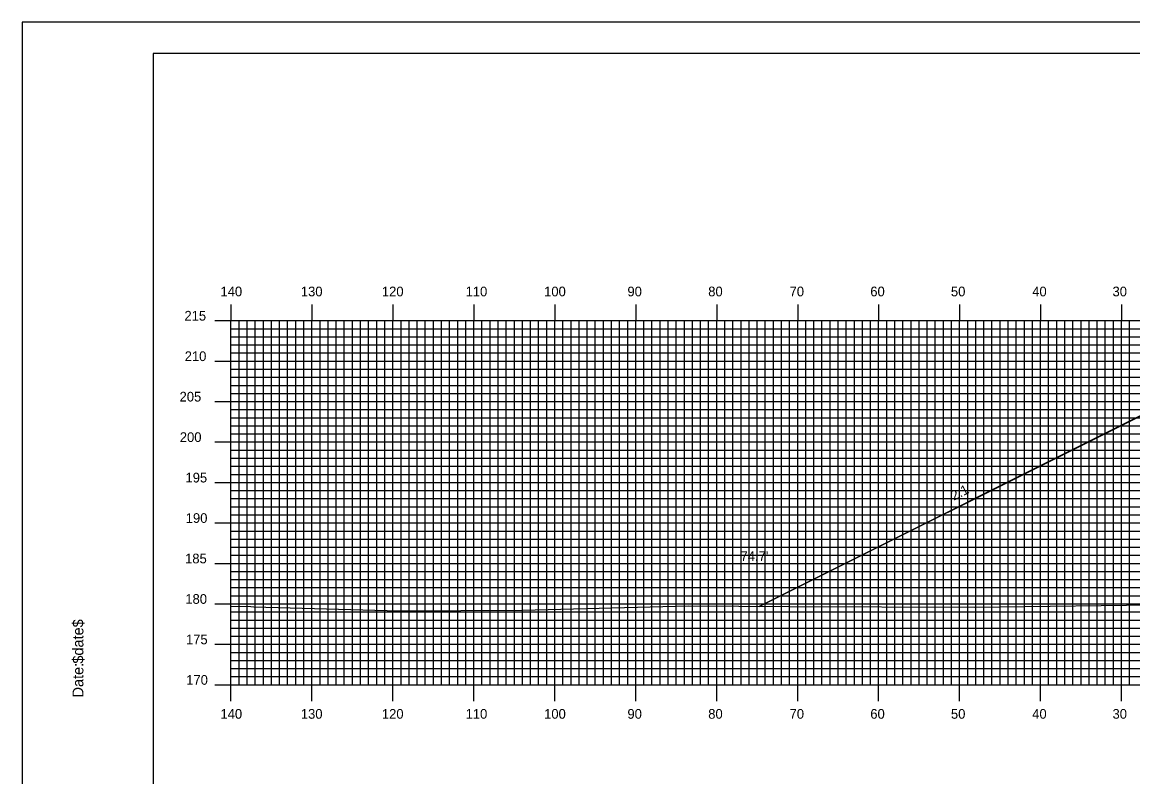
# Model space of a CAD drawing. Extents: x 1809406 to 1809749, y 442591 to 442811.
# Drawn here: x 1809406.1 to 1809543.2, y 442717.3 to 442810.5 of the extents above; entities that cross this region are included whole.
import ezdxf

# ---------------------------------------------------------------- set-up
doc = ezdxf.new("R2010")
doc.units = 0
for name, color, linetype in [('ANNOTATION', 7, 'Continuous'), ('BORDER', 7, 'Continuous'), ('D_Roadway_Centerline', 7, 'Continuous'), ('D_Roadway_SlopeLines', 7, 'Continuous'), ('D_Text_Standard', 7, 'Continuous'), ('H_V ANNOTATION', 7, 'Continuous'), ('MAJOR', 7, 'Continuous'), ('MINOR', 7, 'Continuous'), ('PLOT BOUNDARY', 7, 'Continuous'), ('S_Roadway_Centerline', 7, 'Continuous')]:
    doc.layers.add(name, color=color, linetype=linetype)

msp = doc.modelspace()

# ---------------------------------------------------------------- linework, layer by layer
at = {"layer": 'BORDER'}
msp.add_lwpolyline([(1809422.24, 442596.67), (1809742.24, 442596.67), (1809742.24, 442806.67), (1809422.24, 442806.67)], close=True, dxfattribs=at)
at = {"layer": 'D_Roadway_Centerline'}
msp.add_lwpolyline([(1809497.1, 442738.36), (1809543.63, 442761.62), (1809548.84, 442764.23), (1809551.84, 442764.29), (1809559.84, 442764.45), (1809571.84, 442763.87), (1809583.84, 442763.29), (1809591.84, 442762.91), (1809594.84, 442762.77), (1809600.37, 442760), (1809642.88, 442738.74)], dxfattribs=at)
at = {"layer": 'D_Roadway_SlopeLines'}
msp.add_lwpolyline([(1809548.84, 442764.23), (1809497.1, 442738.36)], dxfattribs=at)
at = {"layer": 'MAJOR'}
for p, q in [((1809431.84, 442775.67), (1809431.84, 442773.67)), ((1809441.84, 442775.67), (1809441.84, 442773.67)), ((1809451.84, 442775.67), (1809451.84, 442773.67)), ((1809461.84, 442775.67), (1809461.84, 442773.67)), ((1809471.84, 442775.67), (1809471.84, 442773.67)), ((1809481.84, 442775.67), (1809481.84, 442773.67)), ((1809491.84, 442775.67), (1809491.84, 442773.67)), ((1809501.84, 442775.67), (1809501.84, 442773.67)), ((1809511.84, 442775.67), (1809511.84, 442773.67)), ((1809521.84, 442775.67), (1809521.84, 442773.67)), ((1809531.84, 442775.67), (1809531.84, 442773.67)), ((1809541.84, 442775.67), (1809541.84, 442773.67)), ((1809429.83, 442773.67), (1809431.84, 442773.67)), ((1809431.84, 442773.67), (1809711.84, 442773.67)), ((1809431.84, 442728.67), (1809431.84, 442773.67)), ((1809431.84, 442728.67), (1809431.84, 442773.67)), ((1809431.84, 442773.67), (1809711.84, 442773.67)), ((1809441.84, 442728.67), (1809441.84, 442773.67)), ((1809451.84, 442728.67), (1809451.84, 442773.67)), ((1809461.84, 442728.67), (1809461.84, 442773.67)), ((1809471.84, 442728.67), (1809471.84, 442773.67)), ((1809481.84, 442728.67), (1809481.84, 442773.67)), ((1809491.84, 442728.67), (1809491.84, 442773.67)), ((1809501.84, 442728.67), (1809501.84, 442773.67)), ((1809511.84, 442728.67), (1809511.84, 442773.67)), ((1809521.84, 442728.67), (1809521.84, 442773.67)), ((1809531.84, 442728.67), (1809531.84, 442773.67)), ((1809541.84, 442728.67), (1809541.84, 442773.67)), ((1809429.83, 442768.67), (1809431.84, 442768.67)), ((1809431.84, 442768.67), (1809711.84, 442768.67)), ((1809429.83, 442763.67), (1809431.84, 442763.67)), ((1809431.84, 442763.67), (1809711.84, 442763.67)), ((1809429.83, 442758.67), (1809431.84, 442758.67)), ((1809431.84, 442758.67), (1809711.84, 442758.67)), ((1809429.83, 442753.67), (1809431.84, 442753.67)), ((1809431.84, 442753.67), (1809711.84, 442753.67)), ((1809429.83, 442748.67), (1809431.84, 442748.67)), ((1809431.84, 442748.67), (1809711.84, 442748.67)), ((1809429.83, 442743.67), (1809431.84, 442743.67)), ((1809431.84, 442743.67), (1809711.84, 442743.67)), ((1809429.83, 442738.67), (1809431.84, 442738.67)), ((1809431.84, 442738.67), (1809711.84, 442738.67)), ((1809429.83, 442733.67), (1809431.84, 442733.67)), ((1809431.84, 442733.67), (1809711.84, 442733.67)), ((1809429.83, 442728.67), (1809431.84, 442728.67)), ((1809431.84, 442728.67), (1809711.84, 442728.67)), ((1809431.84, 442728.67), (1809711.84, 442728.67)), ((1809431.84, 442726.66), (1809431.84, 442728.67)), ((1809441.84, 442726.66), (1809441.84, 442728.67)), ((1809451.84, 442726.66), (1809451.84, 442728.67)), ((1809461.84, 442726.66), (1809461.84, 442728.67)), ((1809471.84, 442726.66), (1809471.84, 442728.67)), ((1809481.84, 442726.66), (1809481.84, 442728.67)), ((1809491.84, 442726.66), (1809491.84, 442728.67)), ((1809501.84, 442726.66), (1809501.84, 442728.67)), ((1809511.84, 442726.66), (1809511.84, 442728.67)), ((1809521.84, 442726.66), (1809521.84, 442728.67)), ((1809531.84, 442726.66), (1809531.84, 442728.67)), ((1809541.84, 442726.66), (1809541.84, 442728.67))]:
    msp.add_line(p, q, dxfattribs=at)
at = {"layer": 'MINOR'}
for p, q in [((1809432.84, 442728.67), (1809432.84, 442773.67)), ((1809433.84, 442728.67), (1809433.84, 442773.67)), ((1809434.84, 442728.67), (1809434.84, 442773.67)), ((1809435.84, 442728.67), (1809435.84, 442773.67)), ((1809436.84, 442728.67), (1809436.84, 442773.67)), ((1809437.84, 442728.67), (1809437.84, 442773.67)), ((1809438.84, 442728.67), (1809438.84, 442773.67)), ((1809439.84, 442728.67), (1809439.84, 442773.67)), ((1809440.84, 442728.67), (1809440.84, 442773.67)), ((1809442.84, 442728.67), (1809442.84, 442773.67)), ((1809443.84, 442728.67), (1809443.84, 442773.67)), ((1809444.84, 442728.67), (1809444.84, 442773.67)), ((1809445.84, 442728.67), (1809445.84, 442773.67)), ((1809446.84, 442728.67), (1809446.84, 442773.67)), ((1809447.84, 442728.67), (1809447.84, 442773.67)), ((1809448.84, 442728.67), (1809448.84, 442773.67)), ((1809449.84, 442728.67), (1809449.84, 442773.67)), ((1809450.84, 442728.67), (1809450.84, 442773.67)), ((1809452.84, 442728.67), (1809452.84, 442773.67)), ((1809453.84, 442728.67), (1809453.84, 442773.67)), ((1809454.84, 442728.67), (1809454.84, 442773.67)), ((1809455.84, 442728.67), (1809455.84, 442773.67)), ((1809456.84, 442728.67), (1809456.84, 442773.67)), ((1809457.84, 442728.67), (1809457.84, 442773.67)), ((1809458.84, 442728.67), (1809458.84, 442773.67)), ((1809459.84, 442728.67), (1809459.84, 442773.67)), ((1809460.84, 442728.67), (1809460.84, 442773.67)), ((1809462.84, 442728.67), (1809462.84, 442773.67)), ((1809463.84, 442728.67), (1809463.84, 442773.67)), ((1809464.84, 442728.67), (1809464.84, 442773.67)), ((1809465.84, 442728.67), (1809465.84, 442773.67)), ((1809466.84, 442728.67), (1809466.84, 442773.67)), ((1809467.84, 442728.67), (1809467.84, 442773.67)), ((1809468.84, 442728.67), (1809468.84, 442773.67)), ((1809469.84, 442728.67), (1809469.84, 442773.67)), ((1809470.84, 442728.67), (1809470.84, 442773.67)), ((1809472.84, 442728.67), (1809472.84, 442773.67)), ((1809473.84, 442728.67), (1809473.84, 442773.67)), ((1809474.84, 442728.67), (1809474.84, 442773.67)), ((1809475.84, 442728.67), (1809475.84, 442773.67)), ((1809476.84, 442728.67), (1809476.84, 442773.67)), ((1809477.84, 442728.67), (1809477.84, 442773.67)), ((1809478.84, 442728.67), (1809478.84, 442773.67)), ((1809479.84, 442728.67), (1809479.84, 442773.67)), ((1809480.84, 442728.67), (1809480.84, 442773.67)), ((1809482.84, 442728.67), (1809482.84, 442773.67)), ((1809483.84, 442728.67), (1809483.84, 442773.67)), ((1809484.84, 442728.67), (1809484.84, 442773.67)), ((1809485.84, 442728.67), (1809485.84, 442773.67)), ((1809486.84, 442728.67), (1809486.84, 442773.67)), ((1809487.84, 442728.67), (1809487.84, 442773.67)), ((1809488.84, 442728.67), (1809488.84, 442773.67)), ((1809489.84, 442728.67), (1809489.84, 442773.67)), ((1809490.84, 442728.67), (1809490.84, 442773.67)), ((1809492.84, 442728.67), (1809492.84, 442773.67)), ((1809493.84, 442728.67), (1809493.84, 442773.67)), ((1809494.84, 442728.67), (1809494.84, 442773.67)), ((1809495.84, 442728.67), (1809495.84, 442773.67)), ((1809496.84, 442728.67), (1809496.84, 442773.67)), ((1809497.84, 442728.67), (1809497.84, 442773.67)), ((1809498.84, 442728.67), (1809498.84, 442773.67)), ((1809499.84, 442728.67), (1809499.84, 442773.67)), ((1809500.84, 442728.67), (1809500.84, 442773.67)), ((1809502.84, 442728.67), (1809502.84, 442773.67)), ((1809503.84, 442728.67), (1809503.84, 442773.67)), ((1809504.84, 442728.67), (1809504.84, 442773.67)), ((1809505.84, 442728.67), (1809505.84, 442773.67)), ((1809506.84, 442728.67), (1809506.84, 442773.67)), ((1809507.84, 442728.67), (1809507.84, 442773.67)), ((1809508.84, 442728.67), (1809508.84, 442773.67)), ((1809509.84, 442728.67), (1809509.84, 442773.67)), ((1809510.84, 442728.67), (1809510.84, 442773.67)), ((1809512.84, 442728.67), (1809512.84, 442773.67)), ((1809513.84, 442728.67), (1809513.84, 442773.67)), ((1809514.84, 442728.67), (1809514.84, 442773.67)), ((1809515.84, 442728.67), (1809515.84, 442773.67)), ((1809516.84, 442728.67), (1809516.84, 442773.67)), ((1809517.84, 442728.67), (1809517.84, 442773.67)), ((1809518.84, 442728.67), (1809518.84, 442773.67)), ((1809519.84, 442728.67), (1809519.84, 442773.67)), ((1809520.84, 442728.67), (1809520.84, 442773.67)), ((1809522.84, 442728.67), (1809522.84, 442773.67)), ((1809523.84, 442728.67), (1809523.84, 442773.67)), ((1809524.84, 442728.67), (1809524.84, 442773.67)), ((1809525.84, 442728.67), (1809525.84, 442773.67)), ((1809526.84, 442728.67), (1809526.84, 442773.67)), ((1809527.84, 442728.67), (1809527.84, 442773.67)), ((1809528.84, 442728.67), (1809528.84, 442773.67)), ((1809529.84, 442728.67), (1809529.84, 442773.67)), ((1809530.84, 442728.67), (1809530.84, 442773.67)), ((1809532.84, 442728.67), (1809532.84, 442773.67)), ((1809533.84, 442728.67), (1809533.84, 442773.67)), ((1809534.84, 442728.67), (1809534.84, 442773.67)), ((1809535.84, 442728.67), (1809535.84, 442773.67)), ((1809536.84, 442728.67), (1809536.84, 442773.67)), ((1809537.84, 442728.67), (1809537.84, 442773.67)), ((1809538.84, 442728.67), (1809538.84, 442773.67)), ((1809539.84, 442728.67), (1809539.84, 442773.67)), ((1809540.84, 442728.67), (1809540.84, 442773.67)), ((1809542.84, 442728.67), (1809542.84, 442773.67)), ((1809431.84, 442772.67), (1809711.84, 442772.67)), ((1809431.84, 442772.67), (1809433.84, 442772.67)), ((1809431.84, 442771.67), (1809711.84, 442771.67)), ((1809431.84, 442771.67), (1809433.84, 442771.67)), ((1809431.84, 442770.67), (1809711.84, 442770.67)), ((1809431.84, 442770.67), (1809433.84, 442770.67)), ((1809431.84, 442769.67), (1809711.84, 442769.67)), ((1809431.84, 442769.67), (1809433.84, 442769.67)), ((1809431.84, 442767.67), (1809711.84, 442767.67)), ((1809431.84, 442767.67), (1809433.84, 442767.67)), ((1809431.84, 442766.67), (1809711.84, 442766.67)), ((1809431.84, 442766.67), (1809433.84, 442766.67)), ((1809431.84, 442765.67), (1809711.84, 442765.67)), ((1809431.84, 442765.67), (1809433.84, 442765.67)), ((1809431.84, 442764.67), (1809711.84, 442764.67)), ((1809431.84, 442764.67), (1809433.84, 442764.67)), ((1809431.84, 442762.67), (1809711.84, 442762.67)), ((1809431.84, 442762.67), (1809433.84, 442762.67)), ((1809431.84, 442761.67), (1809711.84, 442761.67)), ((1809431.84, 442761.67), (1809433.84, 442761.67)), ((1809431.84, 442760.67), (1809711.84, 442760.67)), ((1809431.84, 442760.67), (1809433.84, 442760.67)), ((1809431.84, 442759.67), (1809711.84, 442759.67)), ((1809431.84, 442759.67), (1809433.84, 442759.67)), ((1809431.84, 442757.67), (1809711.84, 442757.67)), ((1809431.84, 442757.67), (1809433.84, 442757.67)), ((1809431.84, 442756.67), (1809711.84, 442756.67)), ((1809431.84, 442756.67), (1809433.84, 442756.67)), ((1809431.84, 442755.67), (1809711.84, 442755.67)), ((1809431.84, 442755.67), (1809433.84, 442755.67)), ((1809431.84, 442754.67), (1809711.84, 442754.67)), ((1809431.84, 442754.67), (1809433.84, 442754.67)), ((1809431.84, 442752.67), (1809711.84, 442752.67)), ((1809431.84, 442752.67), (1809433.84, 442752.67)), ((1809431.84, 442751.67), (1809711.84, 442751.67)), ((1809431.84, 442751.67), (1809433.84, 442751.67)), ((1809431.84, 442750.67), (1809711.84, 442750.67)), ((1809431.84, 442750.67), (1809433.84, 442750.67)), ((1809431.84, 442749.67), (1809711.84, 442749.67)), ((1809431.84, 442749.67), (1809433.84, 442749.67)), ((1809431.84, 442747.67), (1809711.84, 442747.67)), ((1809431.84, 442747.67), (1809433.84, 442747.67)), ((1809431.84, 442746.67), (1809711.84, 442746.67)), ((1809431.84, 442746.67), (1809433.84, 442746.67)), ((1809431.84, 442745.67), (1809711.84, 442745.67)), ((1809431.84, 442745.67), (1809433.84, 442745.67)), ((1809431.84, 442744.67), (1809711.84, 442744.67)), ((1809431.84, 442744.67), (1809433.84, 442744.67)), ((1809431.84, 442742.67), (1809711.84, 442742.67)), ((1809431.84, 442742.67), (1809433.84, 442742.67)), ((1809431.84, 442741.67), (1809711.84, 442741.67)), ((1809431.84, 442741.67), (1809433.84, 442741.67)), ((1809431.84, 442740.67), (1809711.84, 442740.67)), ((1809431.84, 442740.67), (1809433.84, 442740.67)), ((1809431.84, 442739.67), (1809711.84, 442739.67)), ((1809431.84, 442739.67), (1809433.84, 442739.67)), ((1809431.84, 442737.67), (1809711.84, 442737.67)), ((1809431.84, 442737.67), (1809433.84, 442737.67)), ((1809431.84, 442736.67), (1809711.84, 442736.67)), ((1809431.84, 442736.67), (1809433.84, 442736.67)), ((1809431.84, 442735.67), (1809711.84, 442735.67)), ((1809431.84, 442735.67), (1809433.84, 442735.67)), ((1809431.84, 442734.67), (1809711.84, 442734.67)), ((1809431.84, 442734.67), (1809433.84, 442734.67)), ((1809431.84, 442732.67), (1809711.84, 442732.67)), ((1809431.84, 442732.67), (1809433.84, 442732.67)), ((1809431.84, 442731.67), (1809711.84, 442731.67)), ((1809431.84, 442731.67), (1809433.84, 442731.67)), ((1809431.84, 442730.67), (1809711.84, 442730.67)), ((1809431.84, 442730.67), (1809433.84, 442730.67)), ((1809431.84, 442729.67), (1809711.84, 442729.67)), ((1809431.84, 442729.67), (1809433.84, 442729.67))]:
    msp.add_line(p, q, dxfattribs=at)
at = {"layer": 'PLOT BOUNDARY'}
msp.add_lwpolyline([(1809406.05, 442590.55), (1809746.05, 442590.55), (1809746.05, 442810.55), (1809406.05, 442810.55)], close=True, dxfattribs=at)
at = {"layer": 'S_Roadway_Centerline'}
msp.add_lwpolyline([(1809431.84, 442738.37), (1809434.29, 442738.36), (1809434.65, 442738.3), (1809452.6, 442737.8), (1809467.85, 442737.87), (1809488.36, 442738.44), (1809500.77, 442738.32), (1809523.64, 442738.26), (1809548.73, 442738.59), (1809580.88, 442738.83), (1809599.23, 442738.79), (1809626.5, 442738.72), (1809646.18, 442738.75), (1809689.65, 442738.55), (1809701.87, 442738.54), (1809705.77, 442738.66), (1809711.84, 442738.76)], dxfattribs=at)

# ---------------------------------------------------------------- texts
at = {"layer": 'ANNOTATION'}
msp.add_text('2:1', height=1.2, rotation=26.5651, dxfattribs=at).set_placement((1809521.12, 442751.4))
at = {"layer": 'BORDER'}
for s, p in [('$date$', (1809413.61, 442731.28)), ('Date:', (1809413.61, 442727.1))]:
    msp.add_text(s, height=1.339, rotation=90, dxfattribs=at).set_placement(p)
at = {"layer": 'D_Text_Standard'}
msp.add_text("74.7'", height=1.2, dxfattribs=at).set_placement((1809494.78, 442743.97))
at = {"layer": 'H_V ANNOTATION'}
for s, p in [('140', (1809430.54, 442776.67)), ('130', (1809440.47, 442776.67)), ('120', (1809450.48, 442776.67)), ('110', (1809460.82, 442776.67)), ('100', (1809470.52, 442776.67)), ('90', (1809480.81, 442776.67)), ('80', (1809490.79, 442776.67)), ('70', (1809500.84, 442776.67)), ('60', (1809510.81, 442776.67)), ('50', (1809520.77, 442776.67)), ('40', (1809530.81, 442776.67)), ('30', (1809540.73, 442776.67)), ('215', (1809426.09, 442773.67)), ('210', (1809426.12, 442768.67)), ('205', (1809425.49, 442763.67)), ('200', (1809425.52, 442758.67)), ('195', (1809426.22, 442753.67)), ('190', (1809426.25, 442748.67)), ('185', (1809426.17, 442743.67)), ('180', (1809426.2, 442738.67)), ('175', (1809426.28, 442733.67)), ('170', (1809426.31, 442728.67)), ('140', (1809430.54, 442724.47)), ('130', (1809440.47, 442724.47)), ('120', (1809450.48, 442724.47)), ('110', (1809460.82, 442724.47)), ('100', (1809470.52, 442724.47)), ('90', (1809480.81, 442724.47)), ('80', (1809490.79, 442724.47)), ('70', (1809500.84, 442724.47)), ('60', (1809510.81, 442724.47)), ('50', (1809520.77, 442724.47)), ('40', (1809530.81, 442724.47)), ('30', (1809540.73, 442724.47))]:
    msp.add_text(s, height=1.2, dxfattribs=at).set_placement(p)
at = {"layer": 'MAJOR'}
msp.add_text('-', height=0.012, dxfattribs=at).set_placement((1809431.83, 442728.67))

doc.saveas('drawing.dxf')
